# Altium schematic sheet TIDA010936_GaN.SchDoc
size 431 x 279 mm; Date: Not shown in title block; ApprovedBy: Not shown in title block; CheckedBy: Not shown in title block; Author: Not shown in title block; CompanyName: Not shown in title block; DrawnBy: e; Engineer: Not shown in title block; Organization: Not shown in title block; Address1: Not shown in title block; Address2: Not shown in title block; Address3: Not shown in title block; Address4: Not shown in title block; DocumentNumber: 2; Revision: Use project parameter SCH_Rev; SheetNumber: 1; SheetTotal: 2; PageSetup: Record=PageOptions¦CenterHorizontal=True¦CenterVertical=True¦PrintScale=1.00¦XCorrection=1.00¦YCorrection=1.00¦PrintKind=0¦BorderSize=5000000¦LeftOffset=0¦BottomOffset=0¦Orientation=2¦PaperLength=1000¦PaperWidth=1000¦Scale=100¦PaperSource=15¦PrintQuality=600¦MediaType=1¦DitherType=10¦PaperKind=Letter¦PrintScaleMode=1
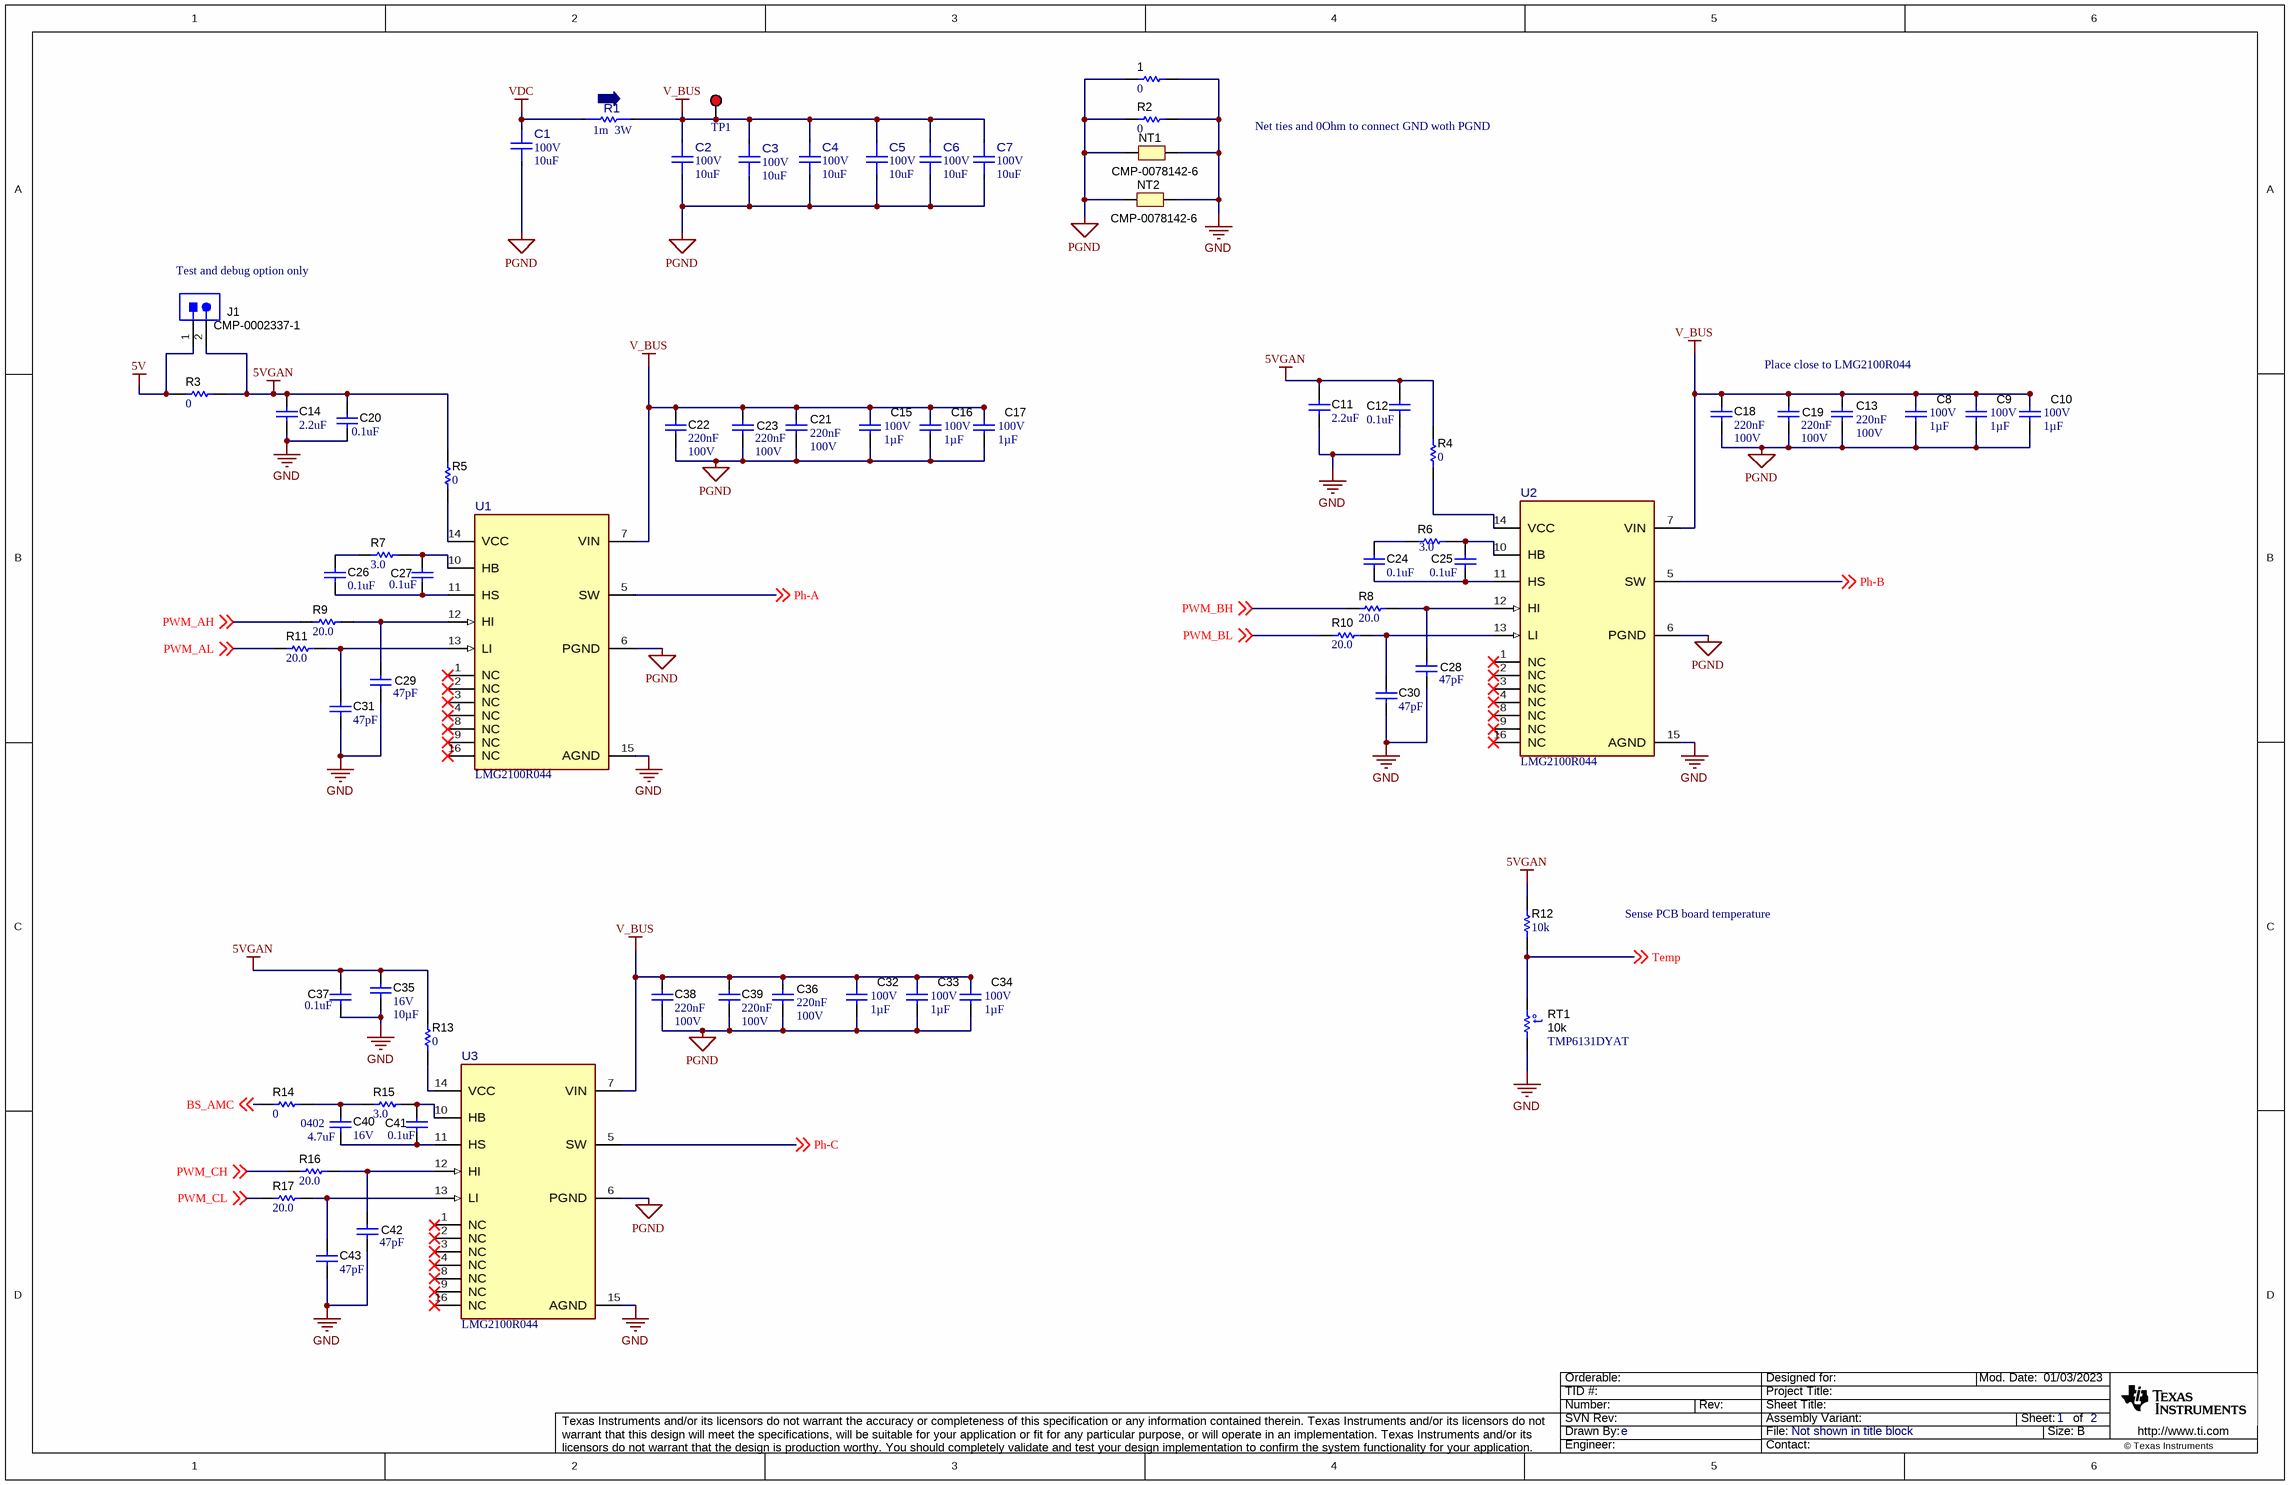
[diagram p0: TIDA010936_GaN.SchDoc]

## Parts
1  ValueDisplayed: 0  [0603]  (hidden comment: CMP-0025883-3)
C1  VDC_V: 100V  ValueDisplayed: 10uF  [FP-C3225X7R2A106K250AC_1210-MFG]  (hidden comment: C3225X7R2A106K250AC)
C2  VDC_V: 100V  ValueDisplayed: 10uF  [FP-C3225X7R2A106K250AC_1210-MFG]  (hidden comment: C3225X7R2A106K250AC)
C3  VDC_V: 100V  ValueDisplayed: 10uF  [FP-C3225X7R2A106K250AC_1210-MFG]  (hidden comment: C3225X7R2A106K250AC)
C4  VDC_V: 100V  ValueDisplayed: 10uF  [FP-C3225X7R2A106K250AC_1210-MFG]  (hidden comment: C3225X7R2A106K250AC)
C5  VDC_V: 100V  ValueDisplayed: 10uF  [FP-C3225X7R2A106K250AC_1210-MFG]  (hidden comment: C3225X7R2A106K250AC)
C6  VDC_V: 100V  ValueDisplayed: 10uF  [FP-C3225X7R2A106K250AC_1210-MFG]  (hidden comment: C3225X7R2A106K250AC)
C7  VDC_V: 100V  ValueDisplayed: 10uF  [FP-C3225X7R2A106K250AC_1210-MFG]  (hidden comment: C3225X7R2A106K250AC)
C8  VDC_V: 100V  ValueDisplayed: 1µF  [0805_HV]  (hidden comment: C2012X7S2A105K125AE)
C9  VDC_V: 100V  ValueDisplayed: 1µF  [0805_HV]  (hidden comment: C2012X7S2A105K125AE)
C10  VDC_V: 100V  ValueDisplayed: 1µF  [0805_HV]  (hidden comment: C2012X7S2A105K125AE)
C11  ValueDisplayed: 2.2uF  [0402_065]  (hidden comment: C1005X7S1A225K050BC)
C12  ValueDisplayed: 0.1uF  [0402]  (hidden comment: CMP-0006351-2)
C13  Cap_F: 220nF  VDC_V: 100V  [0603]  (hidden comment: HMK107C7224KAHTE)
C14  ValueDisplayed: 2.2uF  [0402_065]  (hidden comment: C1005X7S1A225K050BC)
C15  VDC_V: 100V  ValueDisplayed: 1µF  [0805_HV]  (hidden comment: C2012X7S2A105K125AE)
C16  VDC_V: 100V  ValueDisplayed: 1µF  [0805_HV]  (hidden comment: C2012X7S2A105K125AE)
C17  VDC_V: 100V  ValueDisplayed: 1µF  [0805_HV]  (hidden comment: C2012X7S2A105K125AE)
C18  Cap_F: 220nF  VDC_V: 100V  [0603]  (hidden comment: HMK107C7224KAHTE)
C19  Cap_F: 220nF  VDC_V: 100V  [0603]  (hidden comment: HMK107C7224KAHTE)
C20  ValueDisplayed: 0.1uF  [0402]  (hidden comment: CMP-0006351-2)
C21  Cap_F: 220nF  VDC_V: 100V  [0603]  (hidden comment: HMK107C7224KAHTE)
C22  Cap_F: 220nF  VDC_V: 100V  [0603]  (hidden comment: HMK107C7224KAHTE)
C23  Cap_F: 220nF  VDC_V: 100V  [0603]  (hidden comment: HMK107C7224KAHTE)
C24  ValueDisplayed: 0.1uF  [0402]  (hidden comment: CMP-0006351-2)
C25  ValueDisplayed: 0.1uF  [0402]  (hidden comment: CMP-0006351-2)
C26  ValueDisplayed: 0.1uF  [0402]  (hidden comment: CMP-0006351-2)
C27  ValueDisplayed: 0.1uF  [0402]  (hidden comment: CMP-0006351-2)
C28  ValueDisplayed: 47pF  [0402]  (hidden comment: CMP-0006388-2)
C29  ValueDisplayed: 47pF  [0402]  (hidden comment: CMP-0006388-2)
C30  ValueDisplayed: 47pF  [0402]  (hidden comment: CMP-0006388-2)
C31  ValueDisplayed: 47pF  [0402]  (hidden comment: CMP-0006388-2)
C32  VDC_V: 100V  ValueDisplayed: 1µF  [0805_HV]  (hidden comment: C2012X7S2A105K125AE)
C33  VDC_V: 100V  ValueDisplayed: 1µF  [0805_HV]  (hidden comment: C2012X7S2A105K125AE)
C34  VDC_V: 100V  ValueDisplayed: 1µF  [0805_HV]  (hidden comment: C2012X7S2A105K125AE)
C35  VDC_V: 16V  ValueDisplayed: 10µF  [0603]  (hidden comment: GRM188C81C106MA73D)
C36  Cap_F: 220nF  VDC_V: 100V  [0603]  (hidden comment: HMK107C7224KAHTE)
C37  ValueDisplayed: 0.1uF  [0402]  (hidden comment: CMP-0006351-2)
C38  Cap_F: 220nF  VDC_V: 100V  [0603]  (hidden comment: HMK107C7224KAHTE)
C39  Cap_F: 220nF  VDC_V: 100V  [0603]  (hidden comment: HMK107C7224KAHTE)
C40  PackageReference: 0402  VDC_V: 16V  ValueDisplayed: 4.7uF  [0402_070]  (hidden comment: GRM155D81C475ME15D)
C41  ValueDisplayed: 0.1uF  [0402]  (hidden comment: CMP-0006351-2)
C42  ValueDisplayed: 47pF  [0402]  (hidden comment: CMP-0006388-2)
C43  ValueDisplayed: 47pF  [0402]  (hidden comment: CMP-0006388-2)
J1  CMP-0002337-1  [CONN_PEC02SAAN]
NT1  CMP-0078142-6  [Net-Tie_50milWide_30milLong]  (net tie, no BOM)
NT2  CMP-0078142-6  [Net-Tie_50milWide_30milLong]  (net tie, no BOM)
R1  value 1m  Power_W: 3W  [FP-ULRG32512R001FLFSLT_2512-MFG]  (hidden comment: ULRG32512R001FLFSLT)
R2  ValueDisplayed: 0  [0603]  (hidden comment: CMP-0025883-3)
R3  ValueDisplayed: 0  [0402]  (hidden comment: CMP-0026822-3)
R4  ValueDisplayed: 0  [0402]  (hidden comment: CMP-0026822-3)
R5  ValueDisplayed: 0  [0402]  (hidden comment: CMP-0026822-3)
R6  ValueDisplayed: 3.0  [0402]  (hidden comment: CRCW04023R00JNED)
R7  ValueDisplayed: 3.0  [0402]  (hidden comment: CRCW04023R00JNED)
R8  ValueDisplayed: 20.0  [0402]  (hidden comment: CMP-0026164-2)
R9  ValueDisplayed: 20.0  [0402]  (hidden comment: CMP-0026164-2)
R10  ValueDisplayed: 20.0  [0402]  (hidden comment: CMP-0026164-2)
R11  ValueDisplayed: 20.0  [0402]  (hidden comment: CMP-0026164-2)
R12  ValueDisplayed: 10k  [0402]  (hidden comment: CMP-0026825-5)
R13  ValueDisplayed: 0  [0402]  (hidden comment: CMP-0026822-3)
R14  ValueDisplayed: 0  [0402]  (hidden comment: CMP-0026822-3)
R15  ValueDisplayed: 3.0  [0402]  (hidden comment: CRCW04023R00JNED)
R16  ValueDisplayed: 20.0  [0402]  (hidden comment: CMP-0026164-2)
R17  ValueDisplayed: 20.0  [0402]  (hidden comment: CMP-0026164-2)
RT1  value 10k  [DYA0002A-MFG]  (hidden comment: TMP6131DYAT)
TP1  5000  [Keystone5000]  (value not drawn)
U1  LMG2100R044  [RAR0016A-MFG]
U2  LMG2100R044  [RAR0016A-MFG]
U3  LMG2100R044  [RAR0016A-MFG]

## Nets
5V: J1.1 R3.1
5VGAN: C11.1 C12.2 C14.1 C20.1 C35.1 C37.2 J1.2 R3.2 R4.2 R5.2 R12.2 R13.2
GND: 1.2 C11.2 C12.1 C14.2 C20.2 C28.2 C29.2 C30.2 C31.2 C35.2 C37.1 C42.2 C43.2 NT1.2 NT2.2 R2.2 RT1.1 U1.15(AGND) U2.15(AGND) U3.15(AGND)
PGND: 1.1 C1.2 C2.2 C3.1 C4.2 C5.2 C6.2 C7.2 C8.2 C9.2 C10.2 C13.2 C15.2 C16.2 C17.2 C18.2 C19.2 C21.2 C22.2 C23.2 C32.2 C33.2 C34.2 C36.2 C38.2 C39.2 NT1.1 NT2.1 R2.1 U1.6(PGND) U2.6(PGND) U3.6(PGND)
V_BUS: C2.1 C3.2 C4.1 C5.1 C6.1 C7.1 C8.1 C9.1 C10.1 C13.1 C15.1 C16.1 C17.1 C18.1 C19.1 C21.1 C22.1 C23.1 C32.1 C33.1 C34.1 C36.1 C38.1 C39.1 R1.2 TP1.1 U1.7(VIN) U2.7(VIN) U3.7(VIN)
VDC: C1.1 R1.1
BS_AMC: R14.2 ; off-sheet BS_AMC
Ph-A: U1.5(SW) ; off-sheet Ph-A
Ph-B: U2.5(SW) ; off-sheet Ph-B
Ph-C: U3.5(SW) ; off-sheet Ph-C
PWM_AH: R9.2 ; off-sheet PWM_AH
PWM_AL: R11.2 ; off-sheet PWM_AL
PWM_BH: R8.2 ; off-sheet PWM_BH
PWM_BL: R10.2 ; off-sheet PWM_BL
PWM_CH: R16.2 ; off-sheet PWM_CH
PWM_CL: R17.2 ; off-sheet PWM_CL
Temp: R12.1 RT1.2 ; off-sheet Temp
NetC24_1: C24.1 R6.1
NetC24_2: C24.2 C25.2 U2.11(HS)
NetC25_1: C25.1 R6.2 U2.10(HB)
NetC26_1: C26.1 R7.1
NetC26_2: C26.2 C27.2 U1.11(HS)
NetC27_1: C27.1 R7.2 U1.10(HB)
NetC28_1: C28.1 R8.1 U2.12(HI)
NetC29_1: C29.1 R9.1 U1.12(HI)
NetC30_1: C30.1 R10.1 U2.13(LI)
NetC31_1: C31.1 R11.1 U1.13(LI)
NetC40_1: C40.1 R14.1 R15.1
NetC40_2: C40.2 C41.2 U3.11(HS)
NetC41_1: C41.1 R15.2 U3.10(HB)
NetC42_1: C42.1 R16.1 U3.12(HI)
NetC43_1: C43.1 R17.1 U3.13(LI)
NetR4_1: R4.1 U2.14(VCC)
NetR5_1: R5.1 U1.14(VCC)
NetR13_1: R13.1 U3.14(VCC)

Not connected (* = marked no-connect by the designer): U1 1(NC)* 2(NC)* 3(NC)* 4(NC)* 8(NC)* 9(NC)* 16(NC)*; U2 1(NC)* 2(NC)* 3(NC)* 4(NC)* 8(NC)* 9(NC)* 16(NC)*; U3 1(NC)* 2(NC)* 3(NC)* 4(NC)* 8(NC)* 9(NC)* 16(NC)*

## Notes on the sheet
- (near R1) ⬅
- Net ties and 0Ohm to connect GND woth PGND
- (near J1) Test and debug option only
- Place close to LMG2100R044
- Sense PCB board temperature

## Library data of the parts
1 R2 = CMP-0025883-3: RES, 0, 5%, 0.1 W, 0603; PartNumber: MCR03EZPJ000; Manufacturer: Rohm; Value: 0; Value_Code: 0000; Power_W: 100mW; Value2: 0.1W; VDC_V: 50V; TempCo: 400 ppm/C; SizeArea_mm2: 1.28; SizeX_mm: 1.6; SizeY_mm: 0.8; SizeZ_mm: 1; EIA_Code: E24; U/M: EA; AEC Category: Q200; AEC Qualified: N
C1-C7 = CMP-0096021-1: 10 µF ±10% 100V Ceramic Capacitor X7R 1210 (3225 Metric); Manufacturer: TDK; Cap_F: 10µF; AEC Qualified: No; Value: 10µF; SizeZ_mm: 2.85mm; TempCo: 15%
C8-C10 C15-C17 C32-C34 = CMP-0750059-1: CAP, CERM, 1 µF, 100 V,+/- 10%, X7S, 0805; Manufacturer: TDK; TaMax_C: 125°C; SizeAreaWB_mm2: 6.75; SizeY_mm: 1.25; Green_REACh: Incomplete; TaMin_C: -55°C; Cap_Case: 0805; SizeZ_mm: 1.45; U/M: EA; SizeX_mm: 2; Polarized: N; Green_Lifecycle: Active; SizeArea_mm2: 2.5; Value: 1uF; AEC Category: Q200
C11 C14 = CMP-0006302-2: CAP, CERM, 2.2 uF, 10 V, +/- 10%, X7S, 0402; Manufacturer: TDK; Polarized: N; Value: 2.2uF; U/M: EA; Cap_F: 2.2µF; ESR_ohm: 5.925m; Value1: 0.005925 ohm; VDC_V: 10V; IRMS_A: 2.0559A; TaMin_C: -55°C; TaMax_C: 125°C; SizeArea_mm2: 0.5; SizeAreaWB_mm2: 3; SizeX_mm: 1; SizeZ_mm: 0.65; AEC Category: Q200
C12 C20 C24-C27 C37 C41 = CMP-0006351-2: CAP, CERM, 0.1 uF, 16 V, +/- 10%, X7R, 0402; PartNumber: GCM155R71C104KA55D; Manufacturer: MuRata; Polarized: N; Value: 0.1uF; U/M: EA; Cap_F: 100nF; Value1: Unknown; VDC_V: 16V; TaMin_C: -55°C; TaMax_C: 125°C; AEC Category: Q200; SizeAreaWB_mm2: 3; SizeZ_mm: 0.6; SizeX_mm: 1; SizeY_mm: 0.5
C13 C18 C19 C21-C23 C36 C38 C39 = CMP-0077894-3: CAP, CERM, 0.22 µF, 100 V,+/- 10%, X7S, AEC-Q200 Grade 1, 0603; Manufacturer: Taiyo Yuden; TaMin_C: -55°C; Polarized: N; SizeAreaWB_mm2: 4.68; U/M: EA; Value: 0.22uF; TaMax_C: 125°C; SizeZ_mm: 1.0; SizeX_mm: 1.6; SizeY_mm: 0.8; SizeArea_mm2: 1.28; AEC Qualified: Y; AEC Category: Q200; ValueDisplayed: 0.22µF; AEC Grade: 1
C28-C31 C42 C43 = CMP-0006388-2: CAP, CERM, 47 pF, 25 V, +/- 5%, C0G/NP0, 0402; PartNumber: GRM1555C1E470JA01D; Manufacturer: MuRata; Polarized: N; Value: 47pF; U/M: EA; Value1: Unknown; VDC_V: 25V; TaMin_C: -55°C; TaMax_C: 125°C; AEC Category: Q200; SizeAreaWB_mm2: 3; SizeZ_mm: 0.6; SizeX_mm: 1; SizeY_mm: 0.5
C35 = CMP-0086062-1: CAP, CERM, 10 µF, 16 V,+/- 20%, X6S, 0603; Manufacturer: MuRata; U/M: EA; AEC Category: Q200; SizeX_mm: 1.6; SizeY_mm: 0.8; SizeZ_mm: 1; Value: 10uF; SizeArea_mm2: 1.28; TaMin_C: -55°C; Polarized: N; SizeAreaWB_mm2: 4.68; TaMax_C: 105°C
C40 = CMP-0006527-2: CAP, CERM, 4.7 uF, 16 V, +/- 20%, X6T, 0402; Manufacturer: MuRata; TaMin_C: -55°C; Polarized: N; SizeAreaWB_mm2: 3; Value1: Unknown; U/M: EA; Value: 4.7uF; TaMax_C: 105°C; SizeZ_mm: 0.7; SizeX_mm: 1; SizeY_mm: 0.5; Cap_F: 4.7µF; AEC Category: Q200
J1 = CMP-0002337-1: Header, 100mil, 2x1, Tin, TH; PartNumber: PEC02SAAN; Manufacturer: Sullins Connector Solutions; Pitch_mm: 2.54; Gender: Male; Shrouded: N; Row_Count: 1; Current_A: 3A; Voltage_V: 1.8kV; Cert_UL: Y; CNHeader: TRUE; Green_Lifecycle: Not Set; Green_REACh: Incomplete; CT: FALSE
NT1 NT2 = CMP-0078142-6: Single point connection between nets.
R1 = CMP-0042666-1: Res Metal Strip 2512 0.001 Ohm 1% 3W ±50ppm/C Pad SMD Automotive T/R; Manufacturer: TT Electronics; AEC Grade: Grade 0; AEC Qualified: Yes; SizeZ_mm: 0.8mm; TempCo: 50ppm/°C; TaMax_C: +170°C; TaMin_C: -55°C
R3-R5 R13 R14 = CMP-0026822-3: RES, 0, 5%, 0.063 W, AEC-Q200 Grade 0, 0402; PartNumber: CRCW04020000Z0ED; Manufacturer: Vishay-Dale; Value: 0; Value_Code: 0000; Power_W: 63mW; Value2: 0.063W; VDC_V: 50V; TempCo: 200 ppm/C; SizeArea_mm2: 0.5; SizeX_mm: 1; SizeZ_mm: 0.6; EIA_Code: E24; AEC Category: Q200; AEC Qualified: Y
R6 R7 R15 = CMP-0026925-3: RES, 3.0, 5%, 0.063 W, AEC-Q200 Grade 0, 0402; Manufacturer: Vishay-Dale; Power_W: 63mW; TempCo: 200 ppm/C; Value_Code: 3R00; Value: 3.0; EIA_Code: E24; Res_ohm: 3; SizeX_mm: 1; SizeY_mm: 0.5; SizeZ_mm: 0.6; Value2: 0.063W; AEC Qualified: Y; VDC_V: 50V; AEC Category: Q200; AEC Grade: 0
R8-R11 R16 R17 = CMP-0026164-2: RES, 20.0, 1%, 0.063 W, AEC-Q200 Grade 0, 0402; PartNumber: CRCW040220R0FKED; Manufacturer: Vishay-Dale; Value: 20.0; Res_ohm: 20; Value_Code: 20R0; Power_W: 63mW; Value2: 0.063W; VDC_V: 50V; TempCo: 100 ppm/C; EIA_Code: E96; AEC Category: Q200; AEC Qualified: Y; AEC Grade: 0; SizeX_mm: 1; SizeY_mm: 0.5; SizeZ_mm: 0.6
R12 = CMP-0026825-5: RES, 10 k, 5%, 0.063 W, AEC-Q200 Grade 0, 0402; PartNumber: CRCW040210K0JNED; Manufacturer: Vishay-Dale; Value: 10k; Value_Code: 10k0; Power_W: 63mW; Value2: 0.063W; VDC_V: 50V; TempCo: 200 ppm/C; SizeArea_mm2: 0.5; SizeX_mm: 1; SizeZ_mm: 0.6; EIA_Code: E24; AEC Category: Q200; AEC Qualified: Y; AEC Grade: 0
RT1 = CMP-0091865-2: ±1% tolerance 10kΩ linear thermistor available in 0402 and 0603 package options 2-SOT-5X3 -40 to 125; Manufacturer: Texas Instruments; Max Current: 400uA; AEC Qualified: No; TJmax_C: +155°C; TaMin_C: -40°C; TempCo: 6400ppm/°C; TaMax_C: +125°C; VDC_V: 5.5V; SizeZ_mm: 0.77mm; AEC Category: Q200; CompType: IC
TP1 = CMP-0055137-1: Test Point, Miniature, Red, TH; Manufacturer: Keystone; CNHeader: FALSE; Green_Lifecycle: Active; Green_REACh: Passed; ContactFinish: Silver; CT: TRUE
U1-U3 = CMP-0097820-2: Manufacturer: Texas Instruments; AEC Category: Q200; CompType: IC; Standoff Height: 0mm; SizeZ_mm: 0.89mm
